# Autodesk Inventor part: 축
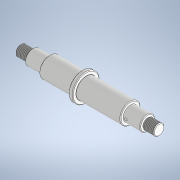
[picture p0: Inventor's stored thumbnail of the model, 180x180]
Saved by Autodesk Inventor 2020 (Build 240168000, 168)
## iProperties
CustomPartVersion: 1
Created: 2021-06
Part Number: 축
Material: 강철, 연강
Document SubType Name: Modeling
Designer: mdu
Density: 1 g/cm^3
Appearance: 흰색
Author: mdu
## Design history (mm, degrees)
sketch "주 스케치"
  geometry: L1 (0, 0)-(203, 0) reference; L2 (0, 0)-(0, 8); L3 (0, 8)-(17, 8); L4 (17, 8)-(17, 11); L5 (17, 11)-(42, 11); L6 (42, 11)-(42, 15); L7 (42, 15)-(90, 15); L8 (90, 15)-(90, 20); L9 (96, 20)-(96, 15); L10 (90, 20)-(96, 20); L11 (161, 15)-(161, 11); L12 (96, 15)-(161, 15); L13 (186, 11)-(186, 8); L14 (161, 11)-(186, 11); L15 (203, 8)-(203, 0); L16 (186, 8)-(203, 8)
  constraints: 32 end point, 9 horizontal, 8 vertical
  dimensions: "d3" = 16 diameter of L3 L1 (derived); "d4" = 22 diameter of L5 L1 (derived); "d5" = 30 diameter of L7 L1 (derived); "d6" = 40 diameter of L10 L1 (derived); "d7" = 30 diameter of L12 L1 (derived); "d8" = 22 diameter of L14 L1 (derived); "d9" = 16 diameter of L16 L1 (derived)
revolve "회전1" sketch "주 스케치" stored, may be unused: angle "d10" = 0 deg
chamfer "모따기1" distance "d11" = 1; stored, may be unused: second distance "d12" = 1, angle "d13" = 45 deg
chamfer "모따기2" distance "d14" = 1; stored, may be unused: second distance "d15" = 1, angle "d16" = 45 deg
node "키홈1"
chamfer "모따기3" distance "d17" = 1; stored, may be unused: second distance "d18" = 1, angle "d19" = 45 deg
fillet "모깎기1" dims "d20" = 0.3
chamfer "모따기4" distance "d21" = 1; stored, may be unused: second distance "d22" = 1, angle "d23" = 45 deg
chamfer "모따기5" distance "d24" = 1; stored, may be unused: second distance "d25" = 1, angle "d26" = 45 deg
fillet "모깎기2" dims "d27" = 0.3
chamfer "모따기6" distance "d28" = 1; stored, may be unused: second distance "d29" = 1, angle "d30" = 45 deg
chamfer "모따기7" distance "d31" = 1; stored, may be unused: second distance "d32" = 1, angle "d33" = 45 deg
node "키홈2"
chamfer "모따기8" distance "d34" = 1; stored, may be unused: second distance "d35" = 1, angle "d36" = 45 deg
sketch "스케치3"
  geometry: L1 (1, 8)-(17, 8) reference; L2 (17, -10)-(17, 10) reference; L3 (186, 10)-(186, -10) reference; L4 (186, 8)-(202, 8) reference; L5 (203, 7)-(203, -7) reference; L6 (0, 0)-(203, 0); L7 (17, 8)-(15.5, 8); L8 (15.5, 8)-(15.5, 7); L9 (15.5, 7)-(17, 7); L10 (17, 7)-(17, 8); L11 (186, 8)-(187.5, 8); L12 (187.5, 8)-(187.5, 7); L13 (187.5, 7)-(186, 7); L14 (186, 7)-(186, 8)
  constraints: 18 end point, 4 parallel, 2 horizontal, 2 perpendicular, 1 midpoint
  dimensions: "d37" = 14 diameter of L13 L6; "d39" = 1.5 distance of L12.end L13.end; "d40" = 14 diameter of L9 L6; "d41" = 1.5 distance of L8.end L9.end
revolve "회전2" sketch "스케치3" stored, may be unused: angle "d42" = 90 deg
feature "스레드1" dims "d43" = 10, "d44" = 0
feature "스레드2" dims "d45" = 10, "d46" = 0
sketch "스케치4"
  geometry: L1 (186, 7)-(186, -7) reference; L2 (186, 10)-(186, -10) reference; L3 (161, -11)-(185, -11) reference; L4 (165, -11)-(165, -9); L5 (165, -9)-(167, -11); L6 (165, -11)-(167, -11); L7 (161, 20)-(161, -20) reference; 1 further point
  constraints: 6 end point, 2 point on line, 1 collinear, 1 perpendicular
  dimensions: "d47" = 21 distance from line of L2 L4.start; "d48" = 4 diameter of L5.end L4; "d49" = 45 deg angle of L4 L5
revolve "회전3" sketch "스케치4" stored, may be unused: angle "d50" = 90 deg
node "솔리드1"
feature "iFeature3:1"
feature "iFeature3:2"
node "투영된 루프1"
node "참조1"
other parameters: "d0" = 0, "d1" = 0, "d2" = 0
